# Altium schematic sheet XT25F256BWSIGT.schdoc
size 127 x 101 mm
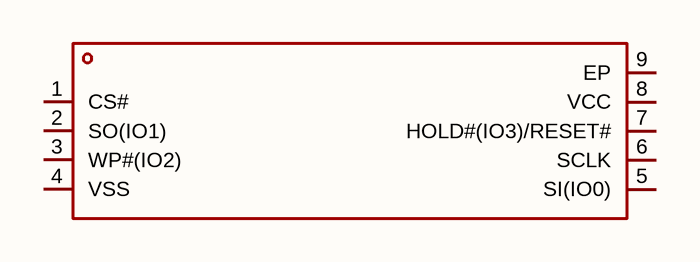
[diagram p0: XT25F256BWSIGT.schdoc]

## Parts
U?  xt25f256bwsigt  [WSON-8_L8.0-W6.0-P1.27-BL-EP-2]  (value not drawn)

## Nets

Not connected (* = marked no-connect by the designer): U? 1(CS#) 2(SO(IO1)) 3(WP#(IO2)) 4(VSS) 5(SI(IO0)) 6(SCLK) 7(HOLD#(IO3)/RESET#) 8(VCC) 9(EP)

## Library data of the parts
U? = xt25f256bwsigt: 接口类型:SPI;存储容量:256Mbit;时钟频率(fc):120MHz;; Manufacturer: XTX(芯天下); AddInBom: yes; Interface: SPI; Clock Frequency: 120MHz; Voltage - Supply: 2.7V~3.6V; Standby Supply Current: 1uA; Program / Erase Cycles: 100000次; Page Programming Time (Tpp): 250us; Data Retention - TDR (Year): 20年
